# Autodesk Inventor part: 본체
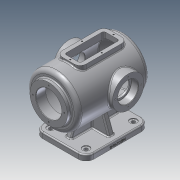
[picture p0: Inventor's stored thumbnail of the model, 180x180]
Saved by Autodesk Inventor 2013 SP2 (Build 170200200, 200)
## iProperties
Created: 2021-11
Part Number: 본체
Material: 알루미늄 6061
Document SubType Name: Modeling
Designer: aa
Density: 2.71 g/cm^3
Mass: 3553.58 g
Surface Area: 2404.15 cm^2
Volume: 1311.28 cm^3
Author: aa
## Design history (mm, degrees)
sketch "스케치1"
  geometry: L1 (0, 0)-(210, 0); L2 (0, 0)-(0, 47.5); L3 (0, 47.5)-(10, 47.5); L4 (10, 47.5)-(10, 65); L5 (10, 65)-(185.993, 65); A1 r 100 centre (110, 0) between (210, 0) and (185.993, 65); 1 further point
  constraints: 10 end point, 2 parallel, 2 perpendicular, 2 point on circle, 1 centre point, 1 coincident, 1 horizontal, 1 horizontal alignment
  dimensions: "d0" = 210 distance of L1.end L1.start; "d1" = 100 radius of A1; "d2" = 95 diameter of L3 L1; "d3" = 130 diameter of L5 L1; "d4" = 10 distance of L2.end L3.end
revolve "회전1" sketch "스케치1" stored, may be unused: angle "d8" = 90 deg
feature "쉘1" dims "d9" = 10
sketch "스케치16"
  geometry: C1 r 55 at (0, 0) reference; C2 r 37.5 at (0, 0) reference; C3 r 55 at (0, 0); C4 r 32.5 at (0, 0)
  constraints: 2 centre point, 2 coincident, 1 concentric
  dimensions: "d121" = 65 diameter of C4
extrude "돌출9" join sketch "스케치16" distance "d122" = 5; taper "d123" = 0 deg
sketch "스케치17"
  geometry: C1 r 32.5 at (0, 0) reference; C2 r 37.5 at (0, 0) reference; C3 r 32.5 at (0, 0)
  constraints: 1 centre point, 1 coincident
  dimensions: "d124" = 65 diameter of C3
extrude "돌출10" join sketch "스케치17" distance "d125" = 20; taper "d126" = 0 deg
node "작업 평면1"
sketch "스케치2"
  geometry: L1 (0, 47.5)-(0, -47.5) reference; L2 (-50, -30)-(-170, -30); L3 (-170, -30)-(-170, 30); L4 (-170, 30)-(-50, 30); L5 (-50, 30)-(-50, -30); 3 further points
  constraints: 8 end point, 2 midpoint, 2 parallel, 1 horizontal, 1 horizontal alignment, 1 perpendicular
  dimensions: "d11" = 120 distance of L3.end L4.end; "d12" = 60 distance of L2.end L3.end; "d13" = 50 distance of point (-50, 0) point (0, 0)
extrude "돌출1" join sketch "스케치2" stored distance "d14" = 25; taper "d15" = 0 deg
fillet "모깎기1" dims "d16" = 15
sketch "스케치3"
  geometry: L1 (65, 30)-(155, 30) reference; L2 (50, -15)-(50, 15) reference; L3 (155, -30)-(65, -30) reference; L4 (170, 15)-(170, -15) reference; L5 (160, 15)-(160, -15); L6 (155, -20)-(65, -20); L7 (60, -15)-(60, 15); L8 (65, 20)-(155, 20); A1 r 15 centre (155, 15) between (170, 15) and (155, 30) reference; A2 r 15 centre (65, 15) between (65, 30) and (50, 15) reference; A3 r 15 centre (65, -15) between (50, -15) and (65, -30) reference; A4 r 15 centre (155, -15) between (155, -30) and (170, -15) reference; A5 r 5 centre (155, 15) between (160, 15) and (155, 20); A6 r 5 centre (155, -15) between (155, -20) and (160, -15); A7 r 5 centre (65, -15) between (60, -15) and (65, -20); A8 r 5 centre (65, 15) between (65, 20) and (60, 15); 1 further point
  constraints: 8 end point, 8 point on circle, 4 centre point, 7 other
  dimensions: "d17" = 10 distance between parallel lines of L1 L8
extrude "돌출2" cut sketch "스케치3" stored distance "d18" = 25; taper "d19" = 0 deg
sketch "스케치4"
  geometry: L1 (65, 30)-(155, 30) reference; L2 (170, 15)-(170, -15) reference; L3 (55, 0)-(165, 0); L4 (110, 25)-(110, -25); 5 further points
  constraints: 5 midpoint, 4 end point, 3 vertical alignment, 2 horizontal alignment, 2 perpendicular
  dimensions: "d20" = 50 distance of L4.start L4.end; "d22" = 110 distance of L3.end L3.start
hole "구멍1" sketch "스케치4" at (55, 0), (110, 25), (110, -25), (165, 0) diameter "d23" = 3.242; stored, may be unused: countersink angle "d27" = 90 deg, drill point angle "d29" = 118 deg; dims "d24" = 9, "d25" = 4, "d26" = 2, "d28" = 11
node "작업 평면2"
sketch "스케치5"
  geometry: L1 (0, -47.5)-(0, 47.5) reference; L2 (0, 0)-(127, 0); C1 r 40 at (127, 0)
  constraints: 2 end point, 1 centre point, 1 coincident, 1 perpendicular
  dimensions: "d31" = 127 distance of L2.start L2.end; "d32" = 80 diameter of C1
extrude "돌출3" join sketch "스케치5" stored distance "d33" = 25; taper "d34" = 0 deg
sketch "스케치6"
  geometry: C1 r 40 at (0, 0) reference; 2 further points
  constraints: 1 coincident
hole "구멍2" sketch "스케치6" at (0, 0) diameter "d35" = 42; stored, may be unused: countersink angle "d39" = 90 deg, drill point angle "d41" = 118 deg; dims "d36" = 9, "d37" = 52, "d38" = 18, "d40" = 75
fillet "모깎기2" dims "d42" = 0.3
sketch "스케치7"
  geometry: C1 r 26 at (0, 0) reference; 5 further points
  constraints: 2 horizontal alignment, 2 vertical alignment
  dimensions: "d44" = 32.5 distance of C1.centre point (0, 32.5); "d45" = 32.5 distance of point (-32.5, 0) C1.centre; "d46" = 32.5 distance of C1.centre point (0, -32.5); "d47" = 32.5 distance of C1.centre point (32.5, 0)
hole "구멍3" sketch "스케치7" at (0, 32.5), (32.5, 0), (-32.5, 0), (0, -32.5) diameter "d48" = 3.242; stored, may be unused: countersink angle "d52" = 90 deg, drill point angle "d54" = 118 deg; dims "d49" = 11, "d50" = 52, "d51" = 18, "d53" = 13
sketch "스케치8"
  geometry: L1 (0, 0)-(0, 40); C1 r 47.5 at (0, 0) reference; 1 further point
  constraints: 2 end point, 1 coincident, 1 vertical
  dimensions: "d55" = 40 distance of L1.start L1.end
hole "구멍4" sketch "스케치8" at (0, 40) diameter "d56" = 3.242; stored, may be unused: countersink angle "d60" = 90 deg, drill point angle "d62" = 118 deg; dims "d57" = 11, "d58" = 52, "d59" = 18, "d61" = 13
node "작업 평면3"
sketch "스케치9"
  geometry: L1 (0, 47.5)-(0, -47.5) reference; L2 (0, 0)-(-30, 0); L3 (-30, -65)-(-190, -65); L4 (-190, -65)-(-190, 65); L5 (-190, 65)-(-30, 65); L6 (-30, 65)-(-30, -65)
  constraints: 10 end point, 2 parallel, 2 perpendicular, 1 horizontal, 1 midpoint
  dimensions: "d67" = 30 distance of L2.end L2.start; "d68" = 160 distance of L4.end L5.end; "d69" = 130 distance of L3.end L4.end
extrude "돌출4" join sketch "스케치9" distance "d70" = 14; taper "d71" = 0 deg
fillet "모깎기3" dims "d72" = 20
node "작업 평면4"
sketch "스케치14"
  geometry: L1 (170, -100)-(50, -100) reference; L2 (30, -100)-(50, -100) reference; L3 (170, -100)-(190, -100) reference; L4 (25, -55)-(181.239, -55) reference; L5 (50, -100)-(63.681, -62.412); L6 (10, -65)-(185.993, -65) reference; L7 (50, -100)-(170, -100); L8 (170, -100)-(156.319, -62.412); L9 (170, -100)-(210, -100); L10 (156.319, -62.412)-(63.681, -62.412); 1 further point
  constraints: 10 end point, 2 point on line, 1 equal length, 1 horizontal
  dimensions: "d98" = 110 deg angle of L2 L5; "d101" = 20 distance of L5.start L2.start; "d102" = 120 distance of L5.start L7.end; "d104" = 40 distance of L5.start L5.end; "d105" = 40 distance of L7.end L8.end; "d106" = 110 deg angle of L9 L8
extrude "돌출8" join sketch "스케치14" stored distance "d107" = 14; taper "d108" = 0 deg
sketch "스케치11"
  geometry: L1 (-100, 65)-(-100, 45) reference; L2 (-100, -45)-(-100, 45) reference; L3 (-55.515, 33.809)-(-100, 50); L4 (-100, 0)-(-100, 50); 2 further points
  constraints: 4 end point, 1 collinear, 1 midpoint, 1 point on line, 2 other
  dimensions: "d80" = 50 distance of L4.start L3.end; "d81" = 110 deg angle of L1 L3
feature "리브1" sketch "스케치11" dims "d82" = 1, "d83" = 14, "d84" = 0, "d85" = 0, "d86" = 1, "d87" = 1
fillet "모깎기4" dims "d96" = 3
fillet "모깎기5" dims "d97" = 3
fillet "모깎기6" dims "d109" = 10
fillet "모깎기7" dims "d110" = 3
chamfer "모따기1" distance "d111" = 1; stored, may be unused: second distance "d112" = 2, angle "d113" = 45 deg
sketch "스케치15"
  geometry: A1 r 17 centre (50, -45) between (33, -45) and (50, -62) reference; A2 r 17 centre (170, -45) between (170, -62) and (187, -45) reference; A3 r 17 centre (170, 45) between (187, 45) and (170, 62) reference; A4 r 17 centre (50, 45) between (50, 62) and (33, 45) reference; 5 further points
  constraints: 4 coincident
hole "구멍5" sketch "스케치15" at (50, 45), (170, 45), (170, -45), (50, -45) diameter "d114" = 9; stored, may be unused: countersink angle "d118" = 90 deg, drill point angle "d120" = 118 deg; dims "d115" = 11, "d116" = 18, "d117" = 2, "d119" = 13
sketch "스케치18"
  geometry: L1 (0, 0)-(120, 0) reference; 3 further points
  constraints: 1 midpoint, 1 vertical alignment, 1 other
  dimensions: "d127" = 5 distance of point (60, 0) point (60, 5)
feature "엠보싱1" sketch "스케치18" dims "d0" = 210, "d1" = 100, "d2" = 95, "d3" = 130, "d4" = 10, "d129" = 0.5, "d130" = 0
fillet "모깎기8" dims "d131" = 3
fillet "모깎기9" dims "d132" = 3
node "솔리드1"
mirror "대칭1"
pattern_circular "원형 패턴1" dims angle "d64" = 360 deg
mirror "대칭2"
other parameters: "d30" = 75, "d66" = -114
